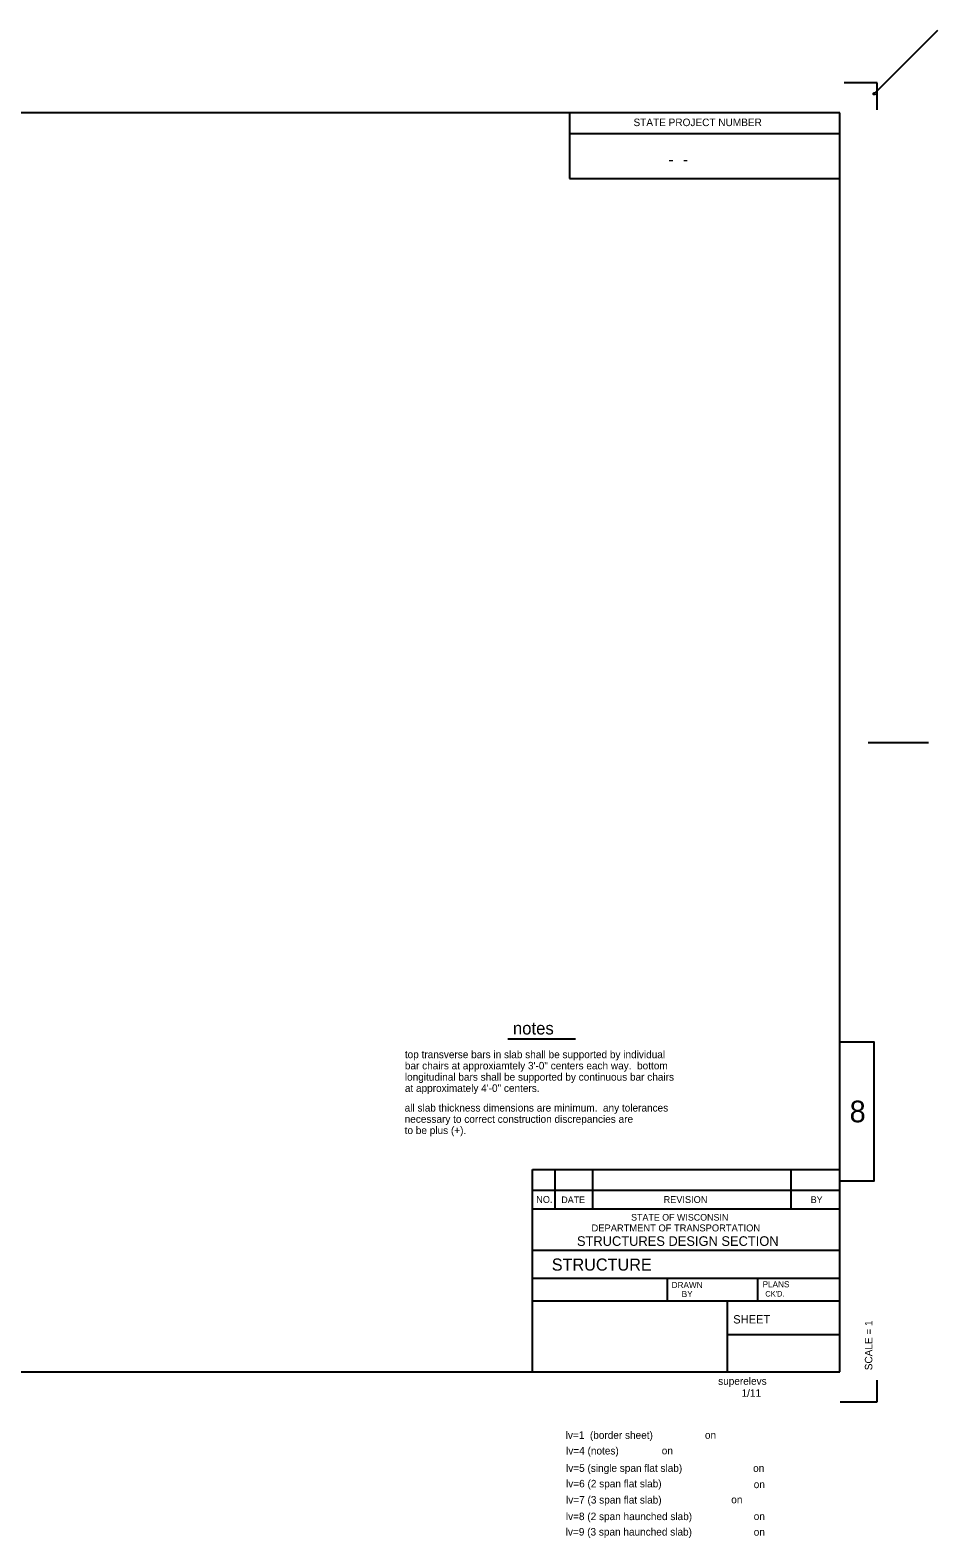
# Model space of a CAD drawing. Extents: x -6.7 to 29.5, y -5.1 to 20.6.
# Drawn here: x 14.35 to 29.49, y -5.1 to 20.04 of the extents above; entities that cross this region are included whole.
import ezdxf

# ---------------------------------------------------------------- set-up
doc = ezdxf.new("R2010")
doc.units = 0
for name, color, linetype in [('Level 1', 7, 'Continuous'), ('Level 2', 7, 'Continuous'), ('Level 37', 7, 'Continuous'), ('Level 4', 7, 'Continuous'), ('Level 49', 7, 'Continuous'), ('Level 5', 7, 'Continuous'), ('Level 6', 7, 'Continuous'), ('Level 7', 7, 'Continuous'), ('Level 8', 7, 'Continuous'), ('Level 9', 7, 'Continuous')]:
    doc.layers.add(name, color=color, linetype=linetype)

msp = doc.modelspace()

# ---------------------------------------------------------------- linework, layer by layer
at = {"layer": 'Level 1'}
for p, q in [((28.481, 19.167), (27.927, 19.167)), ((28.481, 18.712), (28.481, 19.167)), ((27.856, 18.667), (-3.52, 18.667)), ((23.35, 18.667), (23.35, 17.572)), ((27.856, -2.333), (27.856, 18.667)), ((23.35, 18.322), (27.856, 18.322)), ((23.35, 17.572), (27.856, 17.572)), ((22.732, 1.042), (27.859, 1.042)), ((22.732, 0.386), (22.732, 1.042)), ((23.11, 0.386), (23.11, 1.042)), ((23.735, 0.386), (23.735, 1.042)), ((27.047, 0.386), (27.047, 1.042)), ((22.732, 0.698), (27.859, 0.698)), ((22.732, -2.333), (22.732, 0.386)), ((22.732, 0.386), (27.859, 0.386)), ((22.732, -0.301), (27.859, -0.301)), ((22.732, -0.77), (27.859, -0.77)), ((24.982, -1.145), (24.982, -0.77)), ((26.489, -1.145), (26.489, -0.77)), ((22.732, -1.145), (27.859, -1.145)), ((25.981, -2.333), (25.981, -1.145)), ((25.982, -1.708), (27.856, -1.708)), ((-3.52, -2.333), (27.856, -2.333)), ((28.481, -2.833), (28.481, -2.47)), ((27.863, -2.833), (28.481, -2.833))]:
    msp.add_line(p, q, dxfattribs=at)
msp.add_lwpolyline([(27.856, 3.172), (28.423, 3.172), (28.423, 0.851), (27.856, 0.851)], close=True, dxfattribs=at)
at = {"layer": 'Level 2'}
msp.add_line((28.43, 18.983), (29.49, 20.043), dxfattribs=at)
at = {"layer": 'Level 37'}
msp.add_line((28.326, 8.167), (29.336, 8.167), dxfattribs=at)
at = {"layer": 'Level 4'}
msp.add_line((22.317, 3.221), (23.447, 3.221), dxfattribs=at)
at = {"layer": 'Level 49'}
msp.add_circle((28.43, 18.983), 0.0152, dxfattribs=at)

# ---------------------------------------------------------------- texts
at = {"layer": 'Level 1'}
for s, height, p in [('STATE PROJECT NUMBER', 0.12525, (24.415, 18.443)), ('    -  -  ', 0.2023, (24.696, 17.79)), ('8', 0.361, (28.019, 1.831)), ('NO.', 0.1139, (22.793, 0.487)), ('DATE', 0.1109, (23.211, 0.483)), ('REVISION', 0.1142, (24.917, 0.486)), ('BY', 0.1108, (27.371, 0.486)), ('STATE OF WISCONSIN', 0.11076, (24.375, 0.191)), ('DEPARTMENT OF TRANSPORTATION', 0.11643, (23.715, 0.011)), ('STRUCTURES DESIGN SECTION', 0.1605, (23.472, -0.23)), ('STRUCTURE', 0.2022, (23.052, -0.643)), ('DRAWN', 0.1022, (25.051, -0.933)), ('BY', 0.102, (25.219, -1.083)), ('PLANS', 0.1023, (26.567, -0.921)), ("CK'D.", 0.0927, (26.613, -1.075)), ('SHEET', 0.1387, (26.078, -1.524)), ('superelevs', 0.125, (25.827, -2.547)), ('1/11', 0.125, (26.217, -2.746)), ('lv=1  (border sheet)', 0.125, (23.284, -3.448)), ('on', 0.125, (25.606, -3.446)), ('lv=4 (notes)', 0.125, (23.291, -3.709)), ('lv=5 (single span flat slab)', 0.125, (23.29, -3.998)), ('lv=6 (2 span flat slab)', 0.125, (23.29, -4.257)), ('lv=7 (3 span flat slab)', 0.125, (23.29, -4.527)), ('lv=8 (2 span haunched slab)', 0.125, (23.287, -4.803)), ('lv=9 (3 span haunched slab)', 0.125, (23.285, -5.061))]:
    msp.add_text(s, height=height, dxfattribs=at).set_placement(p)
msp.add_text('SCALE = 1        ', height=0.125, rotation=90, dxfattribs=at).set_placement((28.398, -2.304))
at = {"layer": 'Level 4'}
for s, height, p in [('notes', 0.2083, (22.404, 3.295)), ('top transverse bars in slab shall be supported by individual', 0.125, (20.602, 2.9)), ('bar chairs at approxiamtely 3\'-0" centers each way.  bottom', 0.125, (20.602, 2.713)), ('longitudinal bars shall be supported by continuous bar chairs', 0.125, (20.602, 2.525)), ('at approximately 4\'-0" centers.', 0.125, (20.602, 2.338)), ('all slab thickness dimensions are minimum.  any tolerances', 0.125, (20.599, 2.01)), ('to be plus (+).', 0.125, (20.599, 1.635)), ('necessary to correct construction discrepancies are', 0.125, (20.599, 1.822)), ('on', 0.125, (24.886, -3.707))]:
    msp.add_text(s, height=height, dxfattribs=at).set_placement(p)
at = {"layer": 'Level 5'}
msp.add_text('on', height=0.125, dxfattribs=at).set_placement((26.41, -3.999))
at = {"layer": 'Level 6'}
msp.add_text('on', height=0.125, dxfattribs=at).set_placement((26.42, -4.27))
at = {"layer": 'Level 7'}
msp.add_text('on', height=0.125, dxfattribs=at).set_placement((26.045, -4.523))
at = {"layer": 'Level 8'}
msp.add_text('on', height=0.125, dxfattribs=at).set_placement((26.42, -4.802))
at = {"layer": 'Level 9'}
msp.add_text('on', height=0.125, dxfattribs=at).set_placement((26.42, -5.063))

doc.saveas('drawing.dxf')
